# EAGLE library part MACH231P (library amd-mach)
AMD MACH SERIES
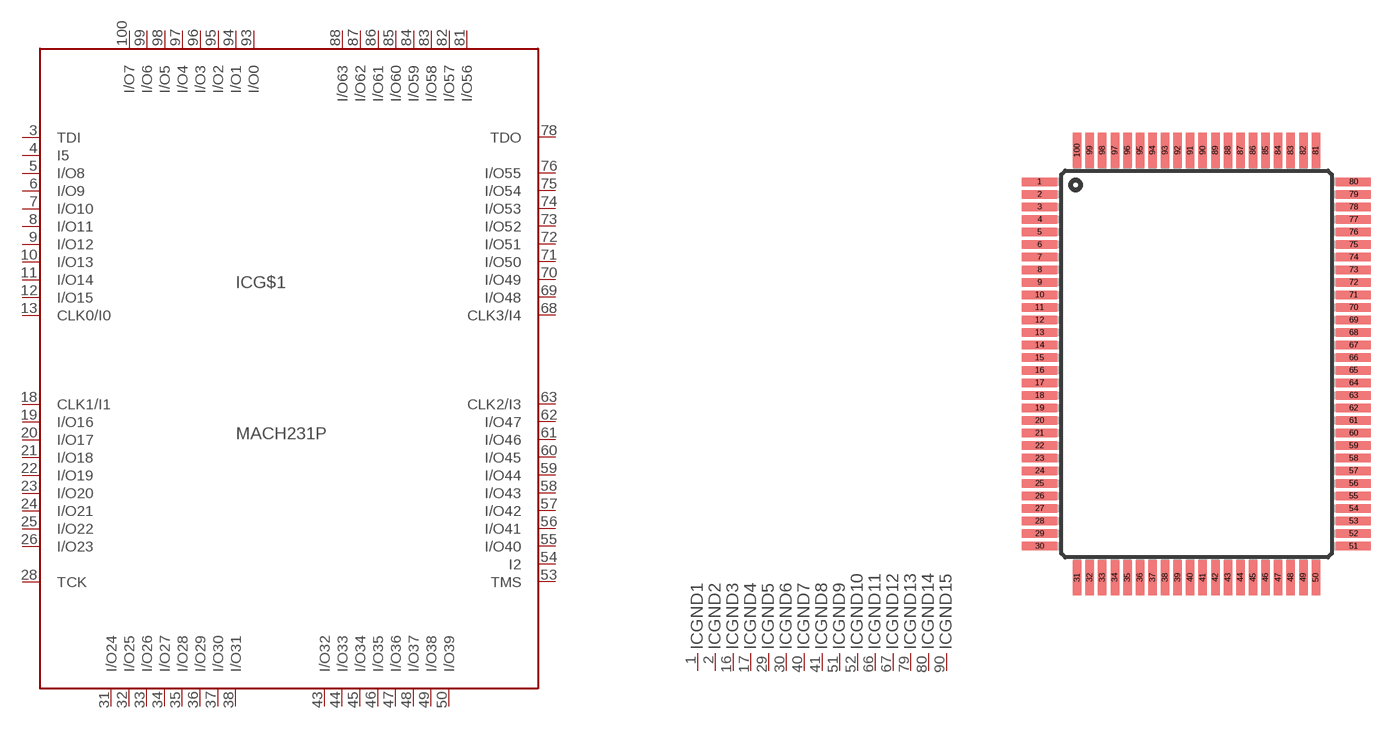
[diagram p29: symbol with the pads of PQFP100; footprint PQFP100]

Designator prefix IC; gates G$1=MACH231P GND1=GND GND2=GND GND3=GND GND4=GND GND5=GND GND6=GND GND7=GND GND8=GND GND9=GND GND10=GND GND11=GND GND12=GND GND13=GND GND14=GND GND15=GND GND16=GND VCC1=VCC VCC2=VCC VCC3=VCC VCC4=VCC VCC5=VCC VCC6=VCC VCC7=VCC VCC8=VCC NC1=NC NC2=NC

## MACH231P (OC_FARNELL: unknown; OC_NEWARK: unknown)  [PQFP100]
1  GND1:GND  pwr
2  GND2:GND  pwr
3  G$1:TDI  in
4  G$1:I5  in
5  G$1:I/O8
6  G$1:I/O9
7  G$1:I/O10
8  G$1:I/O11
9  G$1:I/O12
10  G$1:I/O13
11  G$1:I/O14
12  G$1:I/O15
13  G$1:CLK0/I0  in
14  VCC1:VCC  pwr
15  VCC2:VCC  pwr
16  GND3:GND  pwr
17  GND4:GND  pwr
18  G$1:CLK1/I1  in
19  G$1:I/O16
20  G$1:I/O17
21  G$1:I/O18
22  G$1:I/O19
23  G$1:I/O20
24  G$1:I/O21
25  G$1:I/O22
26  G$1:I/O23
27  NC1:NC  nc
28  G$1:TCK  in
29  GND5:GND  pwr
30  GND6:GND  pwr
31  G$1:I/O24
32  G$1:I/O25
33  G$1:I/O26
34  G$1:I/O27
35  G$1:I/O28
36  G$1:I/O29
37  G$1:I/O30
38  G$1:I/O31
39  VCC3:VCC  pwr
40  GND7:GND  pwr
41  GND8:GND  pwr
42  VCC4:VCC  pwr
43  G$1:I/O32
44  G$1:I/O33
45  G$1:I/O34
46  G$1:I/O35
47  G$1:I/O36
48  G$1:I/O37
49  G$1:I/O38
50  G$1:I/O39
51  GND9:GND  pwr
52  GND10:GND  pwr
53  G$1:TMS  in
54  G$1:I2  in
55  G$1:I/O40
56  G$1:I/O41
57  G$1:I/O42
58  G$1:I/O43
59  G$1:I/O44
60  G$1:I/O45
61  G$1:I/O46
62  G$1:I/O47
63  G$1:CLK2/I3  in
64  VCC5:VCC  pwr
65  VCC6:VCC  pwr
66  GND11:GND  pwr
67  GND12:GND  pwr
68  G$1:CLK3/I4  in
69  G$1:I/O48
70  G$1:I/O49
71  G$1:I/O50
72  G$1:I/O51
73  G$1:I/O52
74  G$1:I/O53
75  G$1:I/O54
76  G$1:I/O55
77  NC2:NC  nc
78  G$1:TDO  in
79  GND13:GND  pwr
80  GND14:GND  pwr
81  G$1:I/O56
82  G$1:I/O57
83  G$1:I/O58
84  G$1:I/O59
85  G$1:I/O60
86  G$1:I/O61
87  G$1:I/O62
88  G$1:I/O63
89  VCC7:VCC  pwr
90  GND15:GND  pwr
91  GND16:GND  pwr
92  VCC8:VCC  pwr
93  G$1:I/O0
94  G$1:I/O1
95  G$1:I/O2
96  G$1:I/O3
97  G$1:I/O4
98  G$1:I/O5
99  G$1:I/O6
100  G$1:I/O7

## Footprint PQFP100 (pad centres in mm)
PLASTIC QUAD FLAT PACK
smd 1.8 x 0.44: 1 -8.125,9.425; 2 -8.125,8.775; 3 -8.125,8.125; 4 -8.125,7.475; 5 -8.125,6.825; 6 -8.125,6.175; 7 -8.125,5.525; 8 -8.125,4.875; 9 -8.125,4.225; 10 -8.125,3.575; 11 -8.125,2.925; 12 -8.125,2.275; 13 -8.125,1.625; 14 -8.125,0.975; 15 -8.125,0.325; 16 -8.125,-0.325; 17 -8.125,-0.975; 18 -8.125,-1.625; 19 -8.125,-2.275; 20 -8.125,-2.925; 21 -8.125,-3.575; 22 -8.125,-4.225; 23 -8.125,-4.875; 24 -8.125,-5.525; 25 -8.125,-6.175; 26 -8.125,-6.825; 27 -8.125,-7.475; 28 -8.125,-8.125; 29 -8.125,-8.775; 30 -8.125,-9.425; 51 8.125,-9.425; 52 8.125,-8.775; 53 8.125,-8.125; 54 8.125,-7.475; 55 8.125,-6.825; 56 8.125,-6.175; 57 8.125,-5.525; 58 8.125,-4.875; 59 8.125,-4.225; 60 8.125,-3.575; 61 8.125,-2.925; 62 8.125,-2.275; 63 8.125,-1.625; 64 8.125,-0.975; 65 8.125,-0.325; 66 8.125,0.325; 67 8.125,0.975; 68 8.125,1.625; 69 8.125,2.275; 70 8.125,2.925; 71 8.125,3.575; 72 8.125,4.225; 73 8.125,4.875; 74 8.125,5.525; 75 8.125,6.175; 76 8.125,6.825; 77 8.125,7.475; 78 8.125,8.125; 79 8.125,8.775; 80 8.125,9.425
smd 0.44 x 1.8: 31 -6.175,-11.05; 32 -5.525,-11.05; 33 -4.875,-11.05; 34 -4.225,-11.05; 35 -3.575,-11.05; 36 -2.925,-11.05; 37 -2.275,-11.05; 38 -1.625,-11.05; 39 -0.975,-11.05; 40 -0.325,-11.05; 41 0.325,-11.05; 42 0.975,-11.05; 43 1.625,-11.05; 44 2.275,-11.05; 45 2.925,-11.05; 46 3.575,-11.05; 47 4.225,-11.05; 48 4.875,-11.05; 49 5.525,-11.05; 50 6.175,-11.05; 81 6.175,11.05; 82 5.525,11.05; 83 4.875,11.05; 84 4.225,11.05; 85 3.575,11.05; 86 2.925,11.05; 87 2.275,11.05; 88 1.625,11.05; 89 0.975,11.05; 90 0.325,11.05; 91 -0.325,11.05; 92 -0.975,11.05; 93 -1.625,11.05; 94 -2.275,11.05; 95 -2.925,11.05; 96 -3.575,11.05; 97 -4.225,11.05; 98 -4.875,11.05; 99 -5.525,11.05; 100 -6.175,11.05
